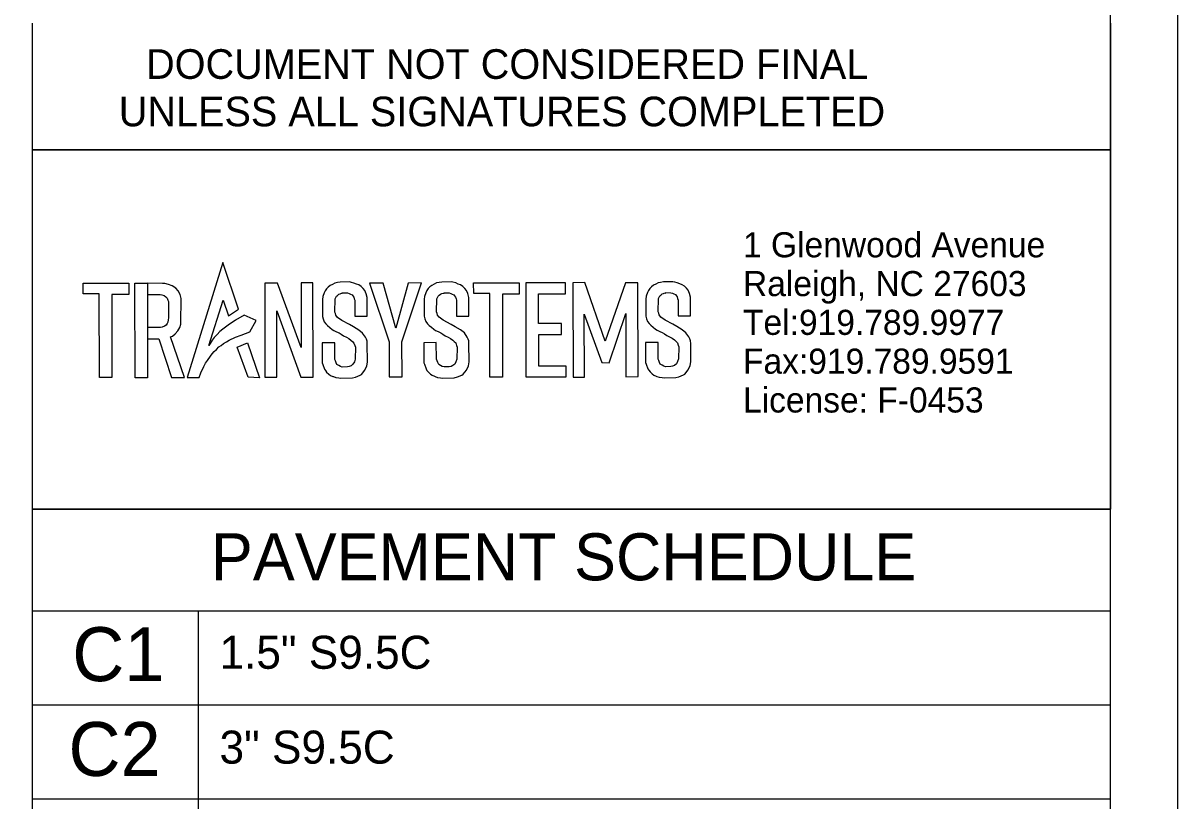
# Model space of a CAD drawing. Extents: x 957297 to 961629, y 830661 to 840840.
# Drawn here: x 960176 to 960390.3, y 836690.3 to 836834.6 of the extents above; entities that cross this region are included whole.
import ezdxf

# ---------------------------------------------------------------- set-up
doc = ezdxf.new("R2010")
doc.units = 0
for name, color, linetype in [('Old_Level_1', 7, 'Continuous'), ('Old_Level_2', 7, 'Continuous'), ('Old_Level_50', 7, 'Continuous'), ('Old_Level_58', 7, 'Continuous'), ('Prop Pavement Schedule Description CELL', 7, 'Continuous'), ('Sheet Plot Border Inside CELL', 7, 'Continuous'), ('Sheet Sticker Exception Certification CELL', 7, 'Continuous'), ('Sheet Typical CELL', 7, 'Continuous')]:
    doc.layers.add(name, color=color, linetype=linetype)

# ---------------------------------------------------------------- blocks, each defined once
blk = doc.blocks.new('TSC-LOGO')
at = {"layer": 'Old_Level_1'}
for points in [[(0.1283, 0.107), (0.0949, 0.0004), (0.106, 0.0004), (0.1077, 0.0046), (0.1106, 0.0104), (0.1121, 0.0136), (0.114, 0.0162), (0.1166, 0.02), (0.1183, 0.0224), (0.1202, 0.0243), (0.1221, 0.0263), (0.1245, 0.0288), (0.1266, 0.0301), (0.1286, 0.0318), (0.1314, 0.0334), (0.1339, 0.0348), (0.14, 0.0376), (0.145, 0.0397), (0.1532, 0.0425), (0.1589, 0.0532), (0.148, 0.058), (0.1399, 0.0535), (0.133, 0.049), (0.1281, 0.045), (0.1254, 0.0429), (0.1228, 0.0401), (0.1201, 0.0373), (0.1181, 0.0351), (0.1162, 0.0319), (0.1151, 0.0301), (0.1283, 0.072), (0.1333, 0.0575), (0.1428, 0.0638)], [(-0.0015, 0.0879), (0.0408, 0.0879), (0.0408, 0.0775), (0.0252, 0.0775), (0.0252, 0.0004), (0.0135, 0.0004), (0.0135, 0.078), (-0.0014, 0.078)], [(0.0466, 0.0878), (0.0581, 0.0878), (0.0581, 0), (0.0466, 0)], [(0.0581, 0.0774), (0.0701, 0.0774), (0.0716, 0.0771), (0.0736, 0.0763), (0.0752, 0.0752), (0.0764, 0.0739), (0.0771, 0.0722), (0.0778, 0.0709), (0.0778, 0.068), (0.0778, 0.0556), (0.0775, 0.0539), (0.0771, 0.0517), (0.0764, 0.0503), (0.0754, 0.0489), (0.0741, 0.0479), (0.0719, 0.0471), (0.0703, 0.0469), (0.0687, 0.0467), (0.0581, 0.0467), (0.0582, 0.0361), (0.0687, 0.0362), (0.0805, 0.0003), (0.0926, 0.0005), (0.0794, 0.0382), (0.0813, 0.0388), (0.084, 0.0408), (0.0864, 0.0435), (0.0882, 0.0467), (0.0892, 0.0498), (0.0892, 0.0508), (0.0894, 0.0736), (0.0884, 0.0773), (0.0866, 0.0807), (0.0845, 0.0831), (0.081, 0.0854), (0.0776, 0.0866), (0.0743, 0.0877), (0.0722, 0.0877), (0.0581, 0.0878)], [(0.1671, 0.0879), (0.1671, 0.0006), (0.1783, 0.0006), (0.1783, 0.062), (0.2005, 0.0005), (0.2118, 0.0006), (0.2117, 0.0881), (0.2008, 0.0881), (0.2009, 0.0282), (0.1789, 0.0879)], [(0.2506, 0.057), (0.2621, 0.057), (0.2621, 0.0744), (0.2612, 0.0779), (0.2598, 0.0808), (0.2583, 0.0828), (0.2564, 0.0845), (0.2542, 0.086), (0.2521, 0.0868), (0.2521, 0.0868), (0.2498, 0.0878), (0.2474, 0.0884), (0.2458, 0.0888), (0.237, 0.0886), (0.2344, 0.0882), (0.2321, 0.0878), (0.2298, 0.0866), (0.2278, 0.0855), (0.2258, 0.0841), (0.2243, 0.0826), (0.223, 0.0807), (0.2221, 0.0788), (0.2208, 0.0753), (0.2205, 0.0727), (0.2205, 0.0569), (0.2211, 0.0545), (0.2222, 0.052), (0.2237, 0.05), (0.2252, 0.0484), (0.2274, 0.0467), (0.2297, 0.0449), (0.2311, 0.0438), (0.2335, 0.0427), (0.2359, 0.0416), (0.2379, 0.0403), (0.2401, 0.0389), (0.2427, 0.0375), (0.2449, 0.0364), (0.247, 0.0349), (0.2486, 0.0334), (0.2498, 0.0322), (0.2506, 0.0298), (0.2511, 0.0283), (0.2509, 0.0171), (0.2501, 0.0147), (0.2488, 0.0126), (0.2472, 0.0111), (0.2454, 0.0103), (0.2437, 0.01), (0.2389, 0.0099), (0.2373, 0.0103), (0.2357, 0.0113), (0.234, 0.0123), (0.2333, 0.0139), (0.2326, 0.0156), (0.232, 0.017), (0.2319, 0.0325), (0.2202, 0.0324), (0.2204, 0.0138), (0.221, 0.0124), (0.2223, 0.0081), (0.2232, 0.0067), (0.2244, 0.0051), (0.2263, 0.0032), (0.2279, 0.0022), (0.23, 0.0013), (0.2308, 0.001), (0.233, 0.0001), (0.2357, -0.0002), (0.2376, -0.0004), (0.2483, -0.0001), (0.2513, 0.0006), (0.2554, 0.0024), (0.2568, 0.0031), (0.2599, 0.007), (0.2616, 0.0109), (0.2624, 0.0145), (0.2621, 0.0316), (0.2621, 0.034), (0.2614, 0.0358), (0.2605, 0.0376), (0.2578, 0.0414), (0.2543, 0.0442), (0.2494, 0.0471), (0.2457, 0.0493), (0.2384, 0.0532), (0.2346, 0.056), (0.2329, 0.0581), (0.2326, 0.0595), (0.2322, 0.0609), (0.2324, 0.0731), (0.233, 0.0744), (0.2337, 0.0756), (0.2346, 0.0764), (0.2357, 0.0774), (0.237, 0.0779), (0.2383, 0.0784), (0.239, 0.0783), (0.2391, 0.0787), (0.2439, 0.0786), (0.2453, 0.078), (0.2467, 0.0775), (0.2481, 0.0769), (0.2487, 0.076), (0.2496, 0.0746), (0.2501, 0.0732), (0.2506, 0.0718), (0.2505, 0.0703)], [(0.277, 0.0878), (0.2643, 0.0878), (0.2823, 0.0334), (0.2825, 0.0007), (0.2944, 0.0008), (0.2943, 0.0332), (0.3126, 0.088), (0.3001, 0.0877), (0.2886, 0.046)], [(0.3449, 0.057), (0.3565, 0.057), (0.3565, 0.0744), (0.3555, 0.0779), (0.3541, 0.0808), (0.3526, 0.0828), (0.3508, 0.0845), (0.3486, 0.086), (0.3465, 0.0868), (0.3465, 0.0868), (0.3442, 0.0878), (0.3417, 0.0884), (0.3401, 0.0888), (0.3314, 0.0886), (0.3288, 0.0882), (0.3265, 0.0878), (0.3242, 0.0866), (0.3221, 0.0855), (0.3202, 0.0841), (0.3186, 0.0826), (0.3174, 0.0807), (0.3164, 0.0788), (0.3152, 0.0753), (0.3149, 0.0727), (0.3149, 0.0569), (0.3155, 0.0545), (0.3166, 0.052), (0.318, 0.05), (0.3195, 0.0484), (0.3218, 0.0467), (0.324, 0.0449), (0.3255, 0.0438), (0.3279, 0.0427), (0.3303, 0.0416), (0.3322, 0.0403), (0.3344, 0.0389), (0.3371, 0.0375), (0.3392, 0.0364), (0.3414, 0.0349), (0.3429, 0.0334), (0.3442, 0.0322), (0.3449, 0.0298), (0.3454, 0.0283), (0.3452, 0.0171), (0.3444, 0.0147), (0.3432, 0.0126), (0.3416, 0.0111), (0.3398, 0.0103), (0.3381, 0.01), (0.3333, 0.0099), (0.3317, 0.0103), (0.33, 0.0113), (0.3284, 0.0123), (0.3277, 0.0139), (0.327, 0.0156), (0.3264, 0.017), (0.3262, 0.0325), (0.3145, 0.0324), (0.3147, 0.0138), (0.3153, 0.0124), (0.3167, 0.0081), (0.3175, 0.0067), (0.3188, 0.0051), (0.3207, 0.0032), (0.3222, 0.0022), (0.3244, 0.0013), (0.3252, 0.001), (0.3273, 0.0001), (0.33, -0.0002), (0.332, -0.0004), (0.3427, -0.0001), (0.3457, 0.0006), (0.3498, 0.0024), (0.3512, 0.0031), (0.3543, 0.007), (0.356, 0.0109), (0.3567, 0.0145), (0.3565, 0.0316), (0.3565, 0.034), (0.3558, 0.0358), (0.3549, 0.0376), (0.3522, 0.0414), (0.3486, 0.0442), (0.3438, 0.0471), (0.34, 0.0493), (0.3327, 0.0532), (0.3289, 0.056), (0.3273, 0.0581), (0.3269, 0.0595), (0.3265, 0.0609), (0.3268, 0.0731), (0.3274, 0.0744), (0.328, 0.0756), (0.3289, 0.0764), (0.3301, 0.0774), (0.3314, 0.0779), (0.3327, 0.0784), (0.3334, 0.0783), (0.3335, 0.0787), (0.3383, 0.0786), (0.3396, 0.078), (0.341, 0.0775), (0.3424, 0.0769), (0.3431, 0.076), (0.344, 0.0746), (0.3445, 0.0732), (0.3449, 0.0718), (0.3449, 0.0703)], [(0.3608, 0.0879), (0.4031, 0.0879), (0.4031, 0.0775), (0.3875, 0.0775), (0.3875, 0.0004), (0.3758, 0.0004), (0.3758, 0.078), (0.3609, 0.078)], [(0.4461, 0.0878), (0.4092, 0.0878), (0.4092, 0.0007), (0.4466, 0.0007), (0.4466, 0.0106), (0.4213, 0.0106), (0.4213, 0.0398), (0.4424, 0.0398), (0.4424, 0.0502), (0.4211, 0.0502), (0.4211, 0.0777), (0.4462, 0.0777)], [(0.4829, 0.0336), (0.4639, 0.0882), (0.4529, 0.0877), (0.4532, 0.0004), (0.4638, 0.0004), (0.4635, 0.0588), (0.4798, 0.0139), (0.4866, 0.0137), (0.502, 0.0593), (0.5021, 0.0007), (0.5135, 0.0008), (0.5133, 0.0879), (0.5018, 0.0878)], [(0.5506, 0.057), (0.5622, 0.057), (0.5622, 0.0744), (0.5612, 0.0779), (0.5598, 0.0808), (0.5583, 0.0828), (0.5564, 0.0845), (0.5542, 0.086), (0.5521, 0.0868), (0.5521, 0.0868), (0.5498, 0.0878), (0.5474, 0.0884), (0.5458, 0.0888), (0.5371, 0.0886), (0.5344, 0.0882), (0.5321, 0.0878), (0.5298, 0.0866), (0.5278, 0.0855), (0.5258, 0.0841), (0.5243, 0.0826), (0.5231, 0.0807), (0.5221, 0.0788), (0.5208, 0.0753), (0.5206, 0.0727), (0.5205, 0.0569), (0.5211, 0.0545), (0.5223, 0.052), (0.5237, 0.05), (0.5252, 0.0484), (0.5274, 0.0467), (0.5297, 0.0449), (0.5311, 0.0438), (0.5335, 0.0427), (0.5359, 0.0416), (0.5379, 0.0403), (0.5401, 0.0389), (0.5427, 0.0375), (0.5449, 0.0364), (0.5471, 0.0349), (0.5486, 0.0334), (0.5499, 0.0322), (0.5506, 0.0298), (0.5511, 0.0283), (0.5509, 0.0171), (0.5501, 0.0147), (0.5489, 0.0126), (0.5472, 0.0111), (0.5454, 0.0103), (0.5437, 0.01), (0.5389, 0.0099), (0.5373, 0.0103), (0.5357, 0.0113), (0.534, 0.0123), (0.5333, 0.0139), (0.5326, 0.0156), (0.5321, 0.017), (0.5319, 0.0325), (0.5202, 0.0324), (0.5204, 0.0138), (0.521, 0.0124), (0.5223, 0.0081), (0.5232, 0.0067), (0.5245, 0.0051), (0.5264, 0.0032), (0.5279, 0.0022), (0.5301, 0.0013), (0.5309, 0.001), (0.533, 0.0001), (0.5357, -0.0002), (0.5376, -0.0004), (0.5483, -0.0001), (0.5513, 0.0006), (0.5554, 0.0024), (0.5568, 0.0031), (0.56, 0.007), (0.5616, 0.0109), (0.5624, 0.0145), (0.5622, 0.0316), (0.5621, 0.034), (0.5615, 0.0358), (0.5605, 0.0376), (0.5578, 0.0414), (0.5543, 0.0442), (0.5494, 0.0471), (0.5457, 0.0493), (0.5384, 0.0532), (0.5346, 0.056), (0.533, 0.0581), (0.5326, 0.0595), (0.5322, 0.0609), (0.5324, 0.0731), (0.5331, 0.0744), (0.5337, 0.0756), (0.5346, 0.0764), (0.5357, 0.0774), (0.537, 0.0779), (0.5383, 0.0784), (0.5391, 0.0783), (0.5391, 0.0787), (0.5439, 0.0786), (0.5453, 0.078), (0.5467, 0.0775), (0.5481, 0.0769), (0.5487, 0.076), (0.5497, 0.0746), (0.5501, 0.0732), (0.5506, 0.0718), (0.5505, 0.0703)], [(0.1413, 0.0285), (0.1509, 0.0323), (0.1622, 0.0001), (0.1517, 0.0005)]]:
    blk.add_lwpolyline(points, close=True, dxfattribs=at)
blk = doc.blocks.new('TRANSYSTEMS Logo')
at = {"layer": 'Old_Level_58'}
blk.add_lwpolyline([(0, 66.69), (200.05, 66.69), (200.05, 0), (0, 0)], close=True, dxfattribs=at)
at = {"layer": 'Old_Level_1', "xscale": 199.99999999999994, "yscale": 199.99999999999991, "rotation": 0.05340743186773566}
blk.add_blockref('TSC-LOGO', (9.71, 24.35), dxfattribs=at)
at = {"layer": 'Old_Level_2'}
for s, p in [('1 Glenwood Avenue', (131.85, 46.73)), ('Raleigh, NC 27603', (131.85, 39.53)), ('Tel:919.789.9977 ', (131.85, 32.34)), ('Fax:919.789.9591', (131.85, 25.14)), ('License: F-0453', (131.85, 17.94))]:
    blk.add_text(s, height=4.6576, rotation=360, dxfattribs=at).set_placement(p)

msp = doc.modelspace()

# ---------------------------------------------------------------- linework, layer by layer
at = {"layer": 'Old_Level_50'}
for p, q in [((960177.75, 836394.2), (960177.75, 836744.41)), ((960177.76, 836744.41), (960377.8, 836744.41)), ((960177.75, 836725.57), (960377.79, 836725.57)), ((960177.75, 836725.57), (960377.79, 836725.57)), ((960208.48, 836725.57), (960208.48, 836394.2)), ((960177.75, 836708.13), (960377.79, 836708.13)), ((960177.75, 836708.13), (960377.79, 836708.13)), ((960177.75, 836708.13), (960377.79, 836708.13)), ((960177.75, 836690.68), (960377.79, 836690.68))]:
    msp.add_line(p, q, dxfattribs=at)
at = {"layer": 'Sheet Plot Border Inside CELL'}
msp.add_lwpolyline([(960390.3, 836974.7), (958723.8, 836974.7), (958723.8, 835919.6), (960390.3, 835919.6)], close=True, dxfattribs=at)
at = {"layer": 'Sheet Sticker Exception Certification CELL'}
for p, q in [((960177.75, 836811.1), (960177.75, 836834.6)), ((960377.79, 836834.59), (960377.79, 836811.09)), ((960377.79, 836811.1), (960177.75, 836811.1))]:
    msp.add_line(p, q, dxfattribs=at)
at = {"layer": 'Sheet Typical CELL'}
msp.add_lwpolyline([(960377.8, 836972.15), (958877.8, 836972.15), (958877.8, 835922.15), (960377.8, 835922.15)], close=True, dxfattribs=at)

# ---------------------------------------------------------------- block references
at = {"layer": 'Old_Level_2'}
msp.add_blockref('TRANSYSTEMS Logo', (960177.74, 836744.41), dxfattribs=at)

# ---------------------------------------------------------------- texts
at = {"layer": 'Old_Level_50'}
msp.add_text('PAVEMENT SCHEDULE', height=8.7206, dxfattribs=at).set_placement((960210.85, 836731.22))
at = {"layer": 'Prop Pavement Schedule Description CELL'}
for s, height, p in [('C1', 10.005, (960185.12, 836712.52)), ('1.5" S9.5C', 6.126, (960212.45, 836714.81)), ('C2', 10.005, (960184.42, 836694.93)), ('3" S9.5C', 6.126, (960212.45, 836697.21))]:
    msp.add_text(s, height=height, dxfattribs=at).set_placement(p)
at = {"layer": 'Sheet Sticker Exception Certification CELL'}
for s, p in [('DOCUMENT NOT CONSIDERED FINAL', (960198.82, 836824.25)), ('UNLESS ALL SIGNATURES COMPLETED', (960193.75, 836815.45))]:
    msp.add_text(s, height=5.5, dxfattribs=at).set_placement(p)

doc.saveas('drawing.dxf')
